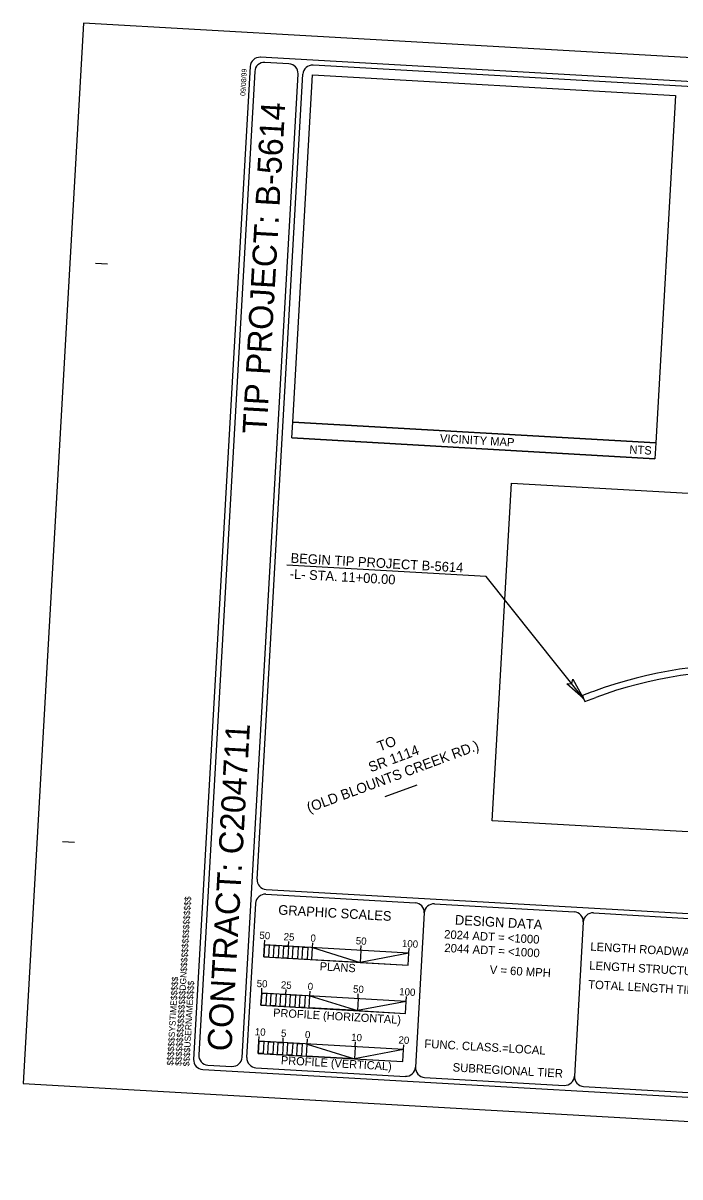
# Model space of a CAD drawing. Extents: x 2601627 to 2606907, y 616646 to 620530.
# Drawn here: x 2601627 to 2603669, y 616945 to 620530 of the extents above; entities that cross this region are included whole.
import ezdxf

# ---------------------------------------------------------------- set-up
doc = ezdxf.new("R2010")
doc.units = 0
for name, color, linetype in [('Exist Roads EOP Leader', 7, 'Continuous'), ('Exist Roads EOP Text', 7, 'Continuous'), ('Prop DSN Text', 7, 'Continuous'), ('Prop Horizontal Alignment Station Label', 7, 'Continuous'), ('Prop Shade Light', 7, 'Continuous'), ('Prop Terminator CELL', 7, 'Continuous'), ('Sheet Data Field CELL', 7, 'Continuous'), ('Sheet Title CELL', 7, 'Continuous'), ('Stewart Plot Border Xerox6279 and LJ5000', 7, 'Continuous')]:
    doc.layers.add(name, color=color, linetype=linetype)

msp = doc.modelspace()

# ---------------------------------------------------------------- linework, layer by layer
at = {"layer": 'Exist Roads EOP Leader'}
msp.add_line((2602752.3, 618126.8), (2602851.8, 618162.7), dxfattribs=at)
at = {"layer": 'Prop Horizontal Alignment Station Label'}
for p, q in [((2603066.8, 618810.4), (2602447.4, 618845.7)), ((2603369.4, 618431.1), (2603066.8, 618810.4))]:
    msp.add_line(p, q, dxfattribs=at)
at = {"layer": 'Prop Shade Light'}
msp.add_line((2603372.9, 618421.7), (2603407.6, 618434.6), dxfattribs=at)
for points in [[(2603400.7, 618453.3), (2603393.3, 618450.6), (2603393.3, 618450.6), (2603365.9, 618440.5)], [(2603365.9, 618440.5), (2603369.4, 618431.1), (2603372.9, 618421.7)]]:
    msp.add_lwpolyline(points, dxfattribs=at)
for radius in [1340, 1320]:
    msp.add_arc((2603866.1, 617196.7), radius, 86.7403, 110.3221, dxfattribs=at)
at = {"layer": 'Prop Terminator CELL'}
msp.add_lwpolyline([(2603336.4, 618491.1), (2603369.4, 618431.1), (2603317.7, 618476.7), (2603332.5, 618477.4)], close=True, dxfattribs=at)
at = {"layer": 'Sheet Data Field CELL'}
for p, q in [((2602377.4, 617665.7), (2602378.3, 617680.7)), ((2602452.3, 617661.4), (2602453.2, 617676.4)), ((2602676.9, 617648.7), (2602677.8, 617663.6)), ((2602826.7, 617640.1), (2602827.6, 617655.1)), ((2602155.6, 617279.9), (2602155.6, 617279.9))]:
    msp.add_line(p, q, dxfattribs=at)
at = {"layer": 'Sheet Title CELL'}
for p, q in [((2602307.9, 617316.3), (2602481.9, 620371.3)), ((2602354.4, 617869.5), (2602496.9, 620370.5)), ((2601852, 619783.7), (2601889.4, 619781.5)), ((2601852, 619783.7), (2601889.4, 619781.5)), ((2603085.2, 618051.6), (2603144.9, 619099.9)), ((2603144.9, 619099.9), (2604442.8, 619026)), ((2604526.6, 617969.5), (2603085.2, 618051.6)), ((2601749.6, 617986.6), (2601787.1, 617984.5)), ((2602382.7, 617837.9), (2606635.8, 617595.6)), ((2602322.9, 617315.4), (2602350.2, 617794.6)), ((2602381.8, 617822.8), (2602846.1, 617796.4)), ((2602906, 617793), (2603340.3, 617768.3)), ((2602874.3, 617764.8), (2602847, 617285.5)), ((2603400.2, 617764.8), (2604538.3, 617700)), ((2603368.5, 617736.6), (2603341.2, 617257.4)), ((2602377.4, 617665.7), (2602378.2, 617680.6)), ((2602378.2, 617680.6), (2602378.2, 617680.6)), ((2602377.4, 617665.7), (2602375.3, 617628.2)), ((2602377.4, 617665.7), (2602377.4, 617665.7)), ((2602826.7, 617640.1), (2602377.4, 617665.7)), ((2602452.3, 617661.4), (2602453.1, 617676.4)), ((2602482.2, 617659.7), (2602480.1, 617622.3)), ((2602527.1, 617657.1), (2602528, 617672.1)), ((2602676.9, 617648.6), (2602674.8, 617611.2)), ((2602676.9, 617648.6), (2602677.8, 617663.6)), ((2602826.7, 617640.1), (2602827.5, 617655.1)), ((2602375.3, 617628.2), (2602824.5, 617602.6)), ((2602824.5, 617602.6), (2602826.7, 617640.1)), ((2602368.9, 617515.9), (2602366.7, 617478.5)), ((2602368.9, 617515.9), (2602369.7, 617530.9)), ((2602368.9, 617515.9), (2602369.7, 617530.9)), ((2602368.9, 617515.9), (2602368.9, 617515.9)), ((2602818.1, 617490.3), (2602368.9, 617515.9)), ((2602368.9, 617515.9), (2602368.9, 617515.9)), ((2602818.1, 617490.3), (2602368.9, 617515.9)), ((2602369.7, 617530.9), (2602369.7, 617530.9)), ((2602443.8, 617511.6), (2602444.6, 617526.6)), ((2602443.8, 617511.6), (2602444.6, 617526.6)), ((2602473.7, 617509.9), (2602471.6, 617472.5)), ((2602518.6, 617507.4), (2602519.5, 617522.3)), ((2602518.6, 617507.4), (2602519.5, 617522.3)), ((2602668.4, 617498.9), (2602669.2, 617513.8)), ((2602668.4, 617498.9), (2602669.2, 617513.8)), ((2602818.1, 617490.3), (2602819, 617505.3)), ((2602818.1, 617490.3), (2602819, 617505.3)), ((2602366.7, 617478.5), (2602816, 617452.9)), ((2602668.4, 617498.9), (2602666.2, 617461.4)), ((2602816, 617452.9), (2602818.1, 617490.3)), ((2602360.4, 617366.1), (2602358.2, 617328.7)), ((2602360.4, 617366.1), (2602361.2, 617381.1)), ((2602360.4, 617366.1), (2602361.2, 617381.1)), ((2602360.4, 617366.1), (2602361.2, 617381.1)), ((2602360.4, 617366.1), (2602360.4, 617366.1)), ((2602809.6, 617340.6), (2602360.4, 617366.1)), ((2602360.4, 617366.1), (2602360.4, 617366.1)), ((2602809.6, 617340.6), (2602360.4, 617366.1)), ((2602360.4, 617366.1), (2602360.4, 617366.1)), ((2602809.6, 617340.6), (2602360.4, 617366.1)), ((2602361.2, 617381.1), (2602361.2, 617381.1)), ((2602435.2, 617361.9), (2602436.1, 617376.8)), ((2602435.2, 617361.9), (2602436.1, 617376.8)), ((2602435.2, 617361.9), (2602436.1, 617376.8)), ((2602465.2, 617360.2), (2602463, 617322.7)), ((2602510.1, 617357.6), (2602511, 617372.6)), ((2602510.1, 617357.6), (2602511, 617372.6)), ((2602510.1, 617357.6), (2602511, 617372.6)), ((2602659.8, 617349.1), (2602660.7, 617364.1)), ((2602659.8, 617349.1), (2602660.7, 617364.1)), ((2602659.8, 617349.1), (2602660.7, 617364.1)), ((2602358.2, 617328.7), (2602807.5, 617303.1)), ((2602659.8, 617349.1), (2602657.7, 617311.6)), ((2602807.5, 617303.1), (2602809.6, 617340.6)), ((2602809.6, 617340.6), (2602810.4, 617355.5)), ((2602809.6, 617340.6), (2602810.4, 617355.5)), ((2602809.6, 617340.6), (2602810.4, 617355.5)), ((2602155.6, 617279.9), (2602155.6, 617279.9)), ((2602155.6, 617279.9), (2602155.6, 617279.9)), ((2602155.6, 617279.9), (2602155.6, 617279.9)), ((2602155.6, 617279.9), (2602155.6, 617279.9))]:
    msp.add_line(p, q, dxfattribs=at)
for points in [[(2606797.5, 620170.6), (2602364.6, 620423.1)], [(2602453.7, 620402.9), (2602378.8, 620407.2)], [(2602333, 620394.8), (2602157.3, 617309.8)], [(2602333, 620394.8), (2602157.3, 617309.8)], [(2602347.2, 620379), (2602173.1, 617323.9)], [(2606781.6, 620156.4), (2602528.6, 620398.7)], [(2602462.6, 619240.5), (2603590.9, 619176.2)], [(2602201.3, 617292.3), (2602276.2, 617288)], [(2602185.5, 617278.1), (2606618.4, 617025.7)], [(2602351.1, 617283.7), (2602815.4, 617257.3)], [(2602875.3, 617253.9), (2603309.6, 617229.2)], [(2603369.5, 617225.7), (2604507.6, 617160.9)]]:
    msp.add_lwpolyline(points, dxfattribs=at)
for points in [[(2602526.9, 620368.9), (2603655.1, 620304.6), (2603593.6, 619225), (2602465.4, 619289.3)], [(2602465.4, 619289.3), (2603593.6, 619225), (2603590.9, 619176.2), (2602462.6, 619240.5)], [(2602377.4, 617665.7), (2602392.4, 617664.8), (2602390.2, 617627.4), (2602375.3, 617628.2)], [(2602407.3, 617664), (2602422.3, 617663.1), (2602420.2, 617625.6), (2602405.2, 617626.5)], [(2602437.3, 617662.2), (2602452.3, 617661.4), (2602450.1, 617624), (2602435.2, 617624.8)], [(2602467.2, 617660.5), (2602482.2, 617659.7), (2602480.1, 617622.3), (2602465.1, 617623.1)], [(2602497.2, 617658.9), (2602512.2, 617658), (2602510, 617620.5), (2602495.1, 617621.4)], [(2602527.1, 617657.1), (2602674.8, 617611.2), (2602525, 617619.7)], [(2602826.7, 617640.1), (2602674.8, 617611.2), (2602824.5, 617602.6)], [(2602368.9, 617515.9), (2602383.8, 617515.1), (2602381.7, 617477.6), (2602366.7, 617478.5)], [(2602398.8, 617514.2), (2602413.8, 617513.4), (2602411.7, 617475.9), (2602396.7, 617476.8)], [(2602428.8, 617512.5), (2602443.8, 617511.6), (2602441.6, 617474.2), (2602426.6, 617475)], [(2602458.7, 617510.8), (2602473.7, 617509.9), (2602471.6, 617472.5), (2602456.6, 617473.4)], [(2602488.7, 617509.1), (2602503.6, 617508.3), (2602501.5, 617470.8), (2602486.5, 617471.7)], [(2602518.6, 617507.4), (2602666.2, 617461.4), (2602516.5, 617469.9)], [(2602818.1, 617490.3), (2602666.2, 617461.4), (2602816, 617452.9)], [(2602360.4, 617366.1), (2602375.3, 617365.3), (2602373.2, 617327.8), (2602358.2, 617328.7)], [(2602390.3, 617364.5), (2602405.3, 617363.6), (2602403.1, 617326.2), (2602388.1, 617327)], [(2602420.2, 617362.8), (2602435.2, 617361.9), (2602433.1, 617324.4), (2602418.1, 617325.3)], [(2602450.2, 617361), (2602465.2, 617360.2), (2602463, 617322.7), (2602448, 617323.6)], [(2602480.1, 617359.3), (2602495.1, 617358.5), (2602493, 617321.1), (2602478, 617321.9)], [(2602510.1, 617357.6), (2602657.7, 617311.6), (2602508, 617320.2)], [(2602809.6, 617340.6), (2602657.7, 617311.6), (2602807.5, 617303.1)]]:
    msp.add_lwpolyline(points, close=True, dxfattribs=at)
for centre, start, end in [((2602363, 620393.3), 86.7403, 176.7403), ((2602377.1, 620377.4), 86.7403, 176.7403), ((2602452, 620373.2), 356.7403, 86.7403), ((2602526.9, 620368.9), 86.7403, 176.7403), ((2602384.4, 617867.9), 176.7403, 266.7403), ((2602380.1, 617793.1), 86.7403, 176.7403), ((2602844.4, 617766.6), 356.7403, 86.7403), ((2602904.3, 617763.2), 86.7403, 176.7403), ((2603338.6, 617738.5), 356.7403, 86.7403), ((2603398.5, 617735.1), 86.7403, 176.7403), ((2602203.1, 617322.4), 176.7403, 266.7403), ((2602187.3, 617308.3), 176.7403, 266.7403), ((2602278, 617318.1), 266.7403, 356.7403), ((2602352.9, 617313.8), 176.7403, 266.7403), ((2602817.1, 617287.4), 266.7403, 356.7403), ((2602877, 617284), 176.7403, 266.7403), ((2603311.3, 617259.3), 266.7403, 356.7403), ((2603371.2, 617255.8), 176.7403, 266.7403)]:
    msp.add_arc(centre, 30, start, end, dxfattribs=at)
at = {"layer": 'Stewart Plot Border Xerox6279 and LJ5000'}
msp.add_lwpolyline([(2601627.1, 617234.9), (2606718.9, 616944.8), (2606906.6, 620239.5), (2601814.8, 620529.5)], close=True, dxfattribs=at)

# ---------------------------------------------------------------- texts
at = {"layer": 'Exist Roads EOP Text'}
for s, p in [('(OLD BLOUNTS CREEK RD.)', (2602516, 618076.1)), ('TO', (2602735.4, 618266.3)), ('SR 1114', (2602707.7, 618201.6))]:
    msp.add_text(s, height=31.5, rotation=20.29, dxfattribs=at).set_placement(p)
at = {"layer": 'Prop DSN Text'}
msp.add_text('VICINITY MAP', height=26.003, rotation=356.7398, dxfattribs=at).set_placement((2602922.3, 619226.9))
at = {"layer": 'Prop Horizontal Alignment Station Label'}
for s, p in [('BEGIN TIP PROJECT B-5614', (2602458.2, 618853.1)), ('-L- STA. 11+00.00', (2602455.4, 618803.9))]:
    msp.add_text(s, height=30, rotation=356.7398, dxfattribs=at).set_placement(p)
at = {"layer": 'Sheet Data Field CELL'}
for s, height, rotation, p in [('50', 22.5, 356.7403, (2602361.3, 617684.6)), ('25', 22.5, 356.7403, (2602436.6, 617680.3)), ('50', 22.5, 356.7403, (2602660.9, 617667.6)), ('100', 22.5, 356.7403, (2602804.4, 617659.4)), ('2024 ADT = <1000', 26.25, 356.7398, (2602935.4, 617686)), ('2044 ADT = <1000', 26.25, 356.7398, (2602936.2, 617643.9)), ('LENGTH ROADWAY TIP PROJECT B-5614', 26.25, 356.747, (2603389.9, 617648)), ('LENGTH STRUCTURES TIP PROJECT B-5614', 26.25, 356.747, (2603386.5, 617589.2)), ('V = 60 MPH', 26.25, 356.7398, (2603077.1, 617576)), ('50', 22.5, 356.7403, (2602352.8, 617534.9)), ('25', 22.5, 356.7403, (2602428, 617530.6)), ('50', 22.5, 356.7403, (2602652.3, 617517.8)), ('TOTAL LENGTH TIP PROJECT B-5614', 26.25, 356.747, (2603383.2, 617530.3)), ('100', 22.5, 356.7403, (2602795.9, 617509.7)), ('10', 22.5, 356.7403, (2602347, 617385)), ('5', 22.5, 356.7403, (2602428.4, 617380.4)), ('10', 22.5, 356.7403, (2602646.5, 617367.9)), ('20', 22.5, 356.7403, (2602793.6, 617359.5)), ('FUNC. CLASS.=LOCAL', 26.25, 356.7398, (2602873.9, 617346.1)), ('SUBREGIONAL TIER', 26.25, 356.7398, (2602961.9, 617272.6))]:
    msp.add_text(s, height=height, rotation=rotation, dxfattribs=at).set_placement(p)
at = {"layer": 'Sheet Title CELL'}
for s, height, rotation, p in [('09/08/99', 15.75, 86.7403, (2602318, 620302.9)), ('TIP PROJECT: B-5614', 75, 86.7403, (2602383.9, 619251.9)), ('NTS', 26, 356.7398, (2603511.2, 619192.4)), ('CONTRACT: C204711', 75, 86.7403, (2602274.7, 617333.5)), ('$$$$$$$$$$$$$$$$DGN$$$$$$$$$$$$$$$$', 19.688, 86.7403, (2602119.4, 617289.5)), ('GRAPHIC SCALES', 29.999, 356.7403, (2602419.8, 617760)), ('DESIGN DATA', 29.999, 356.7398, (2602968.9, 617728.9)), ('0', 22.5, 356.7403, (2602520, 617676)), ('PLANS', 25.5, 356.7403, (2602548.7, 617586.8)), ('$$$$$$SYSTIME$$$$$', 19.688, 86.7403, (2602093.9, 617290.2)), ('$$$$USERNAME$$$$', 19.688, 86.7403, (2602144, 617287.6)), ('0', 22.5, 356.7403, (2602511.4, 617525.8)), ('PROFILE (HORIZONTAL)', 25.499, 356.7403, (2602403.9, 617442.8)), ('0', 22.5, 356.7403, (2602502.9, 617376.1)), ('PROFILE (VERTICAL)', 25.499, 356.7403, (2602428.2, 617295))]:
    msp.add_text(s, height=height, rotation=rotation, dxfattribs=at).set_placement(p)

doc.saveas('drawing.dxf')
